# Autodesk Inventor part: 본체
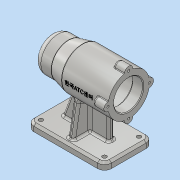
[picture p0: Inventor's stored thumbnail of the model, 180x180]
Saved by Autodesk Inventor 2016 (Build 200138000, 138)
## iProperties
Created: 2019-07
Part Number: 본체
Material: 알루미늄 6061
Document SubType Name: Modeling
Designer: Administrator
Mass: 644.223 g
Surface Area: 653.912 cm^2
Volume: 238.601 cm^3
Density: 2.7 g/cm^3
Appearance: 알루미늄 - 평지
Author: Administrator
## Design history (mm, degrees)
sketch "스케치1"
  geometry: L1 (0, 0)-(30, 0); L2 (30, 0)-(30, 66.631); L3 (29.91, 67.358)-(25.09, 86.642); L4 (25, 87.369)-(25, 102); L5 (15, 112)-(0, 112); L6 (0, 112)-(0, 0); L7 (21, 0)-(21, 15); L8 (21, 15)-(21, 15); L9 (24, 18)-(24, 66); L10 (21, 69)-(21, 69); L11 (21, 69)-(21, 80.7); L12 (20.7, 81)-(17.5, 81); L13 (17.5, 81)-(17.5, 98.7); L14 (17.2, 99)-(16, 99); L15 (16, 99)-(16, 102.7); L16 (15.7, 103)-(10.5, 103); L17 (10.5, 103)-(10.5, 103); L18 (7.5, 106)-(0, 106); A1 r 0.3 centre (15.7, 102.7) between (16, 102.7) and (15.7, 103); A2 r 0.3 centre (17.2, 98.7) between (17.5, 98.7) and (17.2, 99); A3 r 0.3 centre (20.7, 80.7) between (21, 80.7) and (20.7, 81); A4 r 10 centre (15, 102) between (25, 102) and (15, 112); A5 r 3 centre (28, 87.369) between (25, 87.369) and (25.09, 86.642); A6 r 3 centre (27, 66.631) between (30, 66.631) and (29.91, 67.358); A7 r 3 centre (21, 66) between (24, 66) and (21, 69); A8 r 3 centre (21, 18) between (21, 15) and (24, 18); A9 r 3 centre (7.5, 103) between (10.5, 103) and (7.5, 106); 3 further points
  constraints: 36 end point, 18 point on circle, 18 tangent, 14 perpendicular, 9 centre point, 8 point on line, 5 equal radius, 2 horizontal, 1 parallel
  dimensions: "d0" = 112 distance between parallel lines of L1 L5; "d1" = 60 diameter of L2 L6; "d2" = 50 diameter of L4 L6; "d3" = 25 distance of point (25, 87) point (25, 112); "d4" = 45 distance from line of point (30, 67) L5; "d5" = 42 diameter of L7 L6; "d6" = 48 diameter of L9 L6; "d7" = 42 diameter of L11 L6; "d8" = 35 diameter of L13 L6; "d9" = 32 diameter of L15 L6; "d10" = 21 diameter of L17 L6; "d11" = 3 distance between parallel lines of L16 L18; "d12" = 4 distance between parallel lines of L14 L16; "d13" = 18 distance between parallel lines of L12 L14; "d14" = 12 distance between parallel lines of L10 L12; "d15" = 54 distance between parallel lines of L8 L10; "d16" = 15 distance between parallel lines of L1 L8; "d17" = 0.3 radius of A1; "d18" = 10 radius of A4; "d19" = 3 radius of A5; "d20" = 3 radius of A7
revolve "회전1" sketch "스케치1" stored, may be unused: angle "d21" = 90 deg
node "작업 평면1"
sketch "스케치2"
  geometry: L1 (25, 112)-(-25, 112); L2 (-35, 102)-(-35, 10); L3 (-25, 0)-(25, 0); L4 (35, 10)-(35, 102); L5 (-30, 0)-(30, 0) reference; A1 r 10 centre (25, 102) between (35, 102) and (25, 112); A2 r 10 centre (-25, 102) between (-25, 112) and (-35, 102); A3 r 10 centre (-25, 10) between (-35, 10) and (-25, 0); A4 r 10 centre (25, 10) between (25, 0) and (35, 10); 1 further point
  constraints: 8 end point, 8 point on circle, 8 tangent, 4 centre point, 3 equal radius, 2 parallel, 1 collinear, 1 horizontal, 1 perpendicular
  dimensions: "d23" = 112 distance between parallel lines of L3 L1; "d24" = 70 distance between parallel lines of L2 L4; "d25" = 35 distance from line of point (0, 0) L4; "d26" = 10 radius of A1
extrude "돌출1" join sketch "스케치2" distance "d27" = 10; taper "d28" = 0 deg
hole "구멍1" diameter "d31" = 6; stored, may be unused: countersink angle "d35" = 90 deg, drill point angle "d37" = 118 deg; dims "d29" = 10, "d30" = 10, "d32" = 6, "d33" = 4, "d34" = 2, "d36" = 8
node "작업 평면2"
sketch "스케치3"
  geometry: L1 (-25, -70)-(-35, -70) reference; L2 (-28, -70)-(-21.176, -31.302); L3 (35, -70)-(25, -70) reference; L4 (28, -70)-(21.619, -33.809); L5 (-35, -80)-(-35, -70) reference; L6 (35, -80)-(35, -70) reference; 1 further point
  constraints: 4 end point, 2 point on line
  dimensions: "d45" = 7 distance from line of L2.start L5; "d46" = 7 distance from line of L6 L4.start; "d47" = 100 deg angle of L1 L2; "d48" = 100 deg angle of L3 L4
sketch "스케치4"
  geometry: L1 (-4, -60)-(4, -60); L2 (4, -60)-(4, -25); L3 (4, -25)-(-4, -25); L4 (-4, -25)-(-4, -60); L5 (-25, 0)-(25, 0) reference; 1 further point
  constraints: 8 end point, 2 parallel, 1 horizontal, 1 perpendicular
  dimensions: "d49" = 8 distance between parallel lines of L4 L2; "d50" = 4 distance from line of point (0, 0) L4; "d51" = 25 distance between parallel lines of L5 L3; "d52" = 60 distance between parallel lines of L5 L1
extrude "돌출2" join sketch "스케치4" stored distance "d53" = 10; taper "d54" = 0 deg
feature "리브1" dims "d55" = 1, "d56" = 8, "d57" = 0, "d58" = 0, "d59" = 1, "d60" = 1
feature "리브2" dims "d61" = 1, "d62" = 8, "d63" = 0, "d64" = 0, "d65" = 1, "d66" = 1
sketch "스케치5"
  geometry: L1 (-70, 10)-(-70, 102) reference; L2 (-70, 92)-(-43.589, 82.387); L3 (-80, 112)-(-70, 112) reference; 1 further point
  constraints: 2 end point, 1 point on line
  dimensions: "d67" = 20 distance from line of L2.start L3; "d68" = 110 deg angle of L2 L1
feature "리브3" sketch "스케치5" dims "d69" = 1, "d70" = 8, "d71" = 0, "d72" = 0, "d73" = 1, "d74" = 1
sketch "스케치6"
  geometry: C1 r 6 at (0, 29.91); C2 r 6 at (-29.91, 0); C3 r 6 at (0, -29.91); C4 r 6 at (29.91, 0); A1 r 29.91 centre (0, 0) between (4, -29.642) and (-4, -29.642) reference; 6 further points
  constraints: 5 coincident, 4 centre point, 2 vertical alignment, 1 point on circle, 9 other
  dimensions: "d76" = 12 diameter of C1; "d79" = 360 deg dimension on A1.centre C1.centre (derived)
extrude "돌출3" join sketch "스케치6" distance "d81" = 16; taper "d82" = 0 deg
hole "구멍2" sketch "스케치6" diameter "d83" = 3.242; stored, may be unused: countersink angle "d87" = 90 deg, drill point angle "d89" = 118 deg; dims "d84" = 8, "d85" = 4, "d86" = 2, "d88" = 11
chamfer "모따기1" distance "d90" = 3; stored, may be unused: second distance "d91" = 2, angle "d92" = 45 deg
chamfer "모따기2" distance "d93" = 1; stored, may be unused: second distance "d94" = 2, angle "d95" = 45 deg
fillet "모깎기1" dims "d96" = 1, "d97" = 3
node "작업 평면3"
sketch "스케치7"
  geometry: L1 (6.768, -33.315)-(29.227, -33.315) reference; L2 (5.995, -33.315)-(-5.995, -33.315) reference; 3 further points
  constraints: 1 midpoint, 1 vertical alignment, 1 other
  dimensions: "d98" = 42 distance from line of L1 point (0, 8.685)
feature "엠보싱1" sketch "스케치7" dims "d0" = 112, "d1" = 60, "d2" = 50, "d3" = 25, "d4" = 45, "d5" = 42, "d6" = 48, "d7" = 42, "d8" = 35, "d9" = 32, "d10" = 21, "d11" = 3, "d12" = 4, "d13" = 18, "d14" = 12, "d15" = 54, "d16" = 15, "d17" = 0.3, "d18" = 10, "d19" = 3, "d20" = 3, "d99" = 0.5, "d100" = 0
node "솔리드1"
pattern_linear "직사각형 패턴1" dims "d40" = 92
other parameters: "d44" = 56
